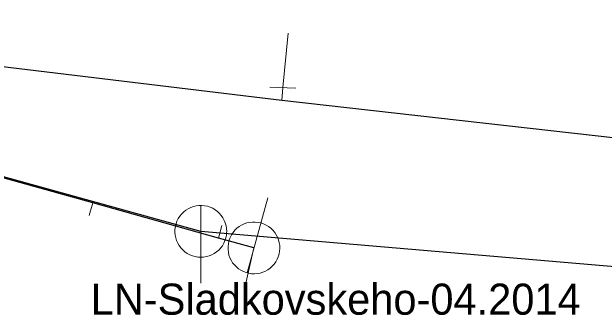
# Model space of a CAD drawing. Extents: x -783064 to -782702, y -1007904 to -1007145.
# Drawn here: x -782776.38 to -782753.52, y -1007576.16 to -1007564.46 of the extents above; entities that cross this region are included whole.
import ezdxf

# ---------------------------------------------------------------- set-up
doc = ezdxf.new("R2010")
doc.units = 0
doc.header["$LTSCALE"] = 0.4
for name, color, linetype, lineweight in [('1', 7, 'Continuous', 13), ('11', 7, 'Continuous', 13), ('13', 7, 'Continuous', 13), ('14', 7, 'Continuous', 13), ('17', 7, 'Continuous', 25), ('22', 7, 'Continuous', 13), ('34', 7, 'Continuous', 13)]:
    doc.layers.add(name, color=color, linetype=linetype, lineweight=lineweight)

msp = doc.modelspace()

# ---------------------------------------------------------------- linework, layer by layer
at = {"layer": '11'}
for p, q in [((-782773.399, -1007572.32), (-782773.26, -1007571.83)), ((-782768.28, -1007572.7), (-782768.41, -1007573.19)), ((-782767.399, -1007575.16), (-782767.039, -1007573.57))]:
    msp.add_line(p, q, dxfattribs=at)
at = {"layer": '13'}
for p, q in [((-782765.926, -1007567.38), (-782765.721, -1007565.282)), ((-782765.967, -1007567.884), (-782765.926, -1007567.38))]:
    msp.add_line(p, q, dxfattribs=at)
at = {"layer": '14', "lineweight": 25}
for p, q in [((-782769.09, -1007572.93), (-782798.949, -1007564.67)), ((-782749.991, -1007574.563), (-782769.09, -1007572.93))]:
    msp.add_line(p, q, dxfattribs=at)
msp.add_lwpolyline([(-782767.039, -1007573.57), (-782768.41, -1007573.19), (-782773.26, -1007571.83), (-782779.129, -1007570.2), (-782798.949, -1007564.67)], dxfattribs=at)
at = {"layer": '17'}
msp.add_lwpolyline([(-782721.948, -1007572.833), (-782724.344, -1007572.563), (-782743.599, -1007570.399), (-782747.826, -1007569.923), (-782765.967, -1007567.884), (-782794.359, -1007564.46)], dxfattribs=at)
at = {"layer": '22'}
for p, q in [((-782766.504, -1007571.642), (-782767.306, -1007574.533)), ((-782769.09, -1007574.93), (-782769.089, -1007571.93))]:
    msp.add_line(p, q, dxfattribs=at)
for points in [[(-782768.09, -1007572.93), (-782768.095, -1007572.821), (-782768.113, -1007572.713), (-782768.143, -1007572.607), (-782768.183, -1007572.506), (-782768.235, -1007572.409), (-782768.297, -1007572.319), (-782768.369, -1007572.236), (-782768.449, -1007572.162), (-782768.537, -1007572.096), (-782768.631, -1007572.041), (-782768.731, -1007571.996), (-782768.836, -1007571.963), (-782768.943, -1007571.941), (-782769.052, -1007571.931), (-782769.162, -1007571.933), (-782769.27, -1007571.947), (-782769.377, -1007571.972), (-782769.48, -1007572.009), (-782769.578, -1007572.058), (-782769.67, -1007572.116), (-782769.756, -1007572.185), (-782769.833, -1007572.262), (-782769.902, -1007572.348), (-782769.961, -1007572.44), (-782770.009, -1007572.538), (-782770.046, -1007572.641), (-782770.072, -1007572.748), (-782770.086, -1007572.856), (-782770.089, -1007572.966), (-782770.079, -1007573.075), (-782770.058, -1007573.182), (-782770.024, -1007573.286), (-782769.98, -1007573.386), (-782769.925, -1007573.481), (-782769.859, -1007573.569), (-782769.785, -1007573.649), (-782769.702, -1007573.721), (-782769.612, -1007573.783), (-782769.516, -1007573.835), (-782769.414, -1007573.876), (-782769.309, -1007573.906), (-782769.201, -1007573.924), (-782769.091, -1007573.93), (-782768.982, -1007573.924), (-782768.874, -1007573.906), (-782768.769, -1007573.877), (-782768.667, -1007573.836), (-782768.57, -1007573.784), (-782768.48, -1007573.722), (-782768.397, -1007573.651), (-782768.322, -1007573.571), (-782768.257, -1007573.483), (-782768.201, -1007573.389), (-782768.157, -1007573.289), (-782768.123, -1007573.185), (-782768.101, -1007573.077), (-782768.091, -1007572.968)], [(-782768.002, -1007573.302), (-782768.025, -1007573.408), (-782768.037, -1007573.517), (-782768.036, -1007573.627), (-782768.025, -1007573.735), (-782768.001, -1007573.843), (-782767.965, -1007573.946), (-782767.918, -1007574.045), (-782767.86, -1007574.138), (-782767.793, -1007574.225), (-782767.717, -1007574.303), (-782767.633, -1007574.373), (-782767.541, -1007574.433), (-782767.443, -1007574.483), (-782767.341, -1007574.522), (-782767.235, -1007574.549), (-782767.127, -1007574.565), (-782767.017, -1007574.569), (-782766.908, -1007574.561), (-782766.8, -1007574.54), (-782766.696, -1007574.509), (-782766.595, -1007574.465), (-782766.5, -1007574.412), (-782766.411, -1007574.347), (-782766.329, -1007574.274), (-782766.257, -1007574.193), (-782766.193, -1007574.103), (-782766.14, -1007574.007), (-782766.097, -1007573.907), (-782766.066, -1007573.801), (-782766.047, -1007573.694), (-782766.038, -1007573.585), (-782766.043, -1007573.476), (-782766.059, -1007573.367), (-782766.086, -1007573.261), (-782766.127, -1007573.159), (-782766.176, -1007573.062), (-782766.237, -1007572.97), (-782766.307, -1007572.887), (-782766.386, -1007572.811), (-782766.473, -1007572.744), (-782766.566, -1007572.687), (-782766.666, -1007572.641), (-782766.77, -1007572.606), (-782766.877, -1007572.582), (-782766.986, -1007572.571), (-782767.095, -1007572.571), (-782767.204, -1007572.583), (-782767.311, -1007572.607), (-782767.414, -1007572.643), (-782767.513, -1007572.689), (-782767.607, -1007572.746), (-782767.693, -1007572.813), (-782767.772, -1007572.889), (-782767.841, -1007572.974), (-782767.902, -1007573.065), (-782767.952, -1007573.163), (-782767.991, -1007573.265)]]:
    msp.add_lwpolyline(points, close=True, dxfattribs=at)
at = {"layer": '34'}
msp.add_line((-782766.425, -1007567.36), (-782765.426, -1007567.4), dxfattribs=at)

# ---------------------------------------------------------------- texts
at = {"layer": '1'}
msp.add_text('LN-Sladkovskeho-04.2014 ', height=1.2, dxfattribs=at).set_placement((-782773.34, -1007576.146))

doc.saveas('drawing.dxf')
